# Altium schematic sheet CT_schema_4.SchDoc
size 298 x 230 mm
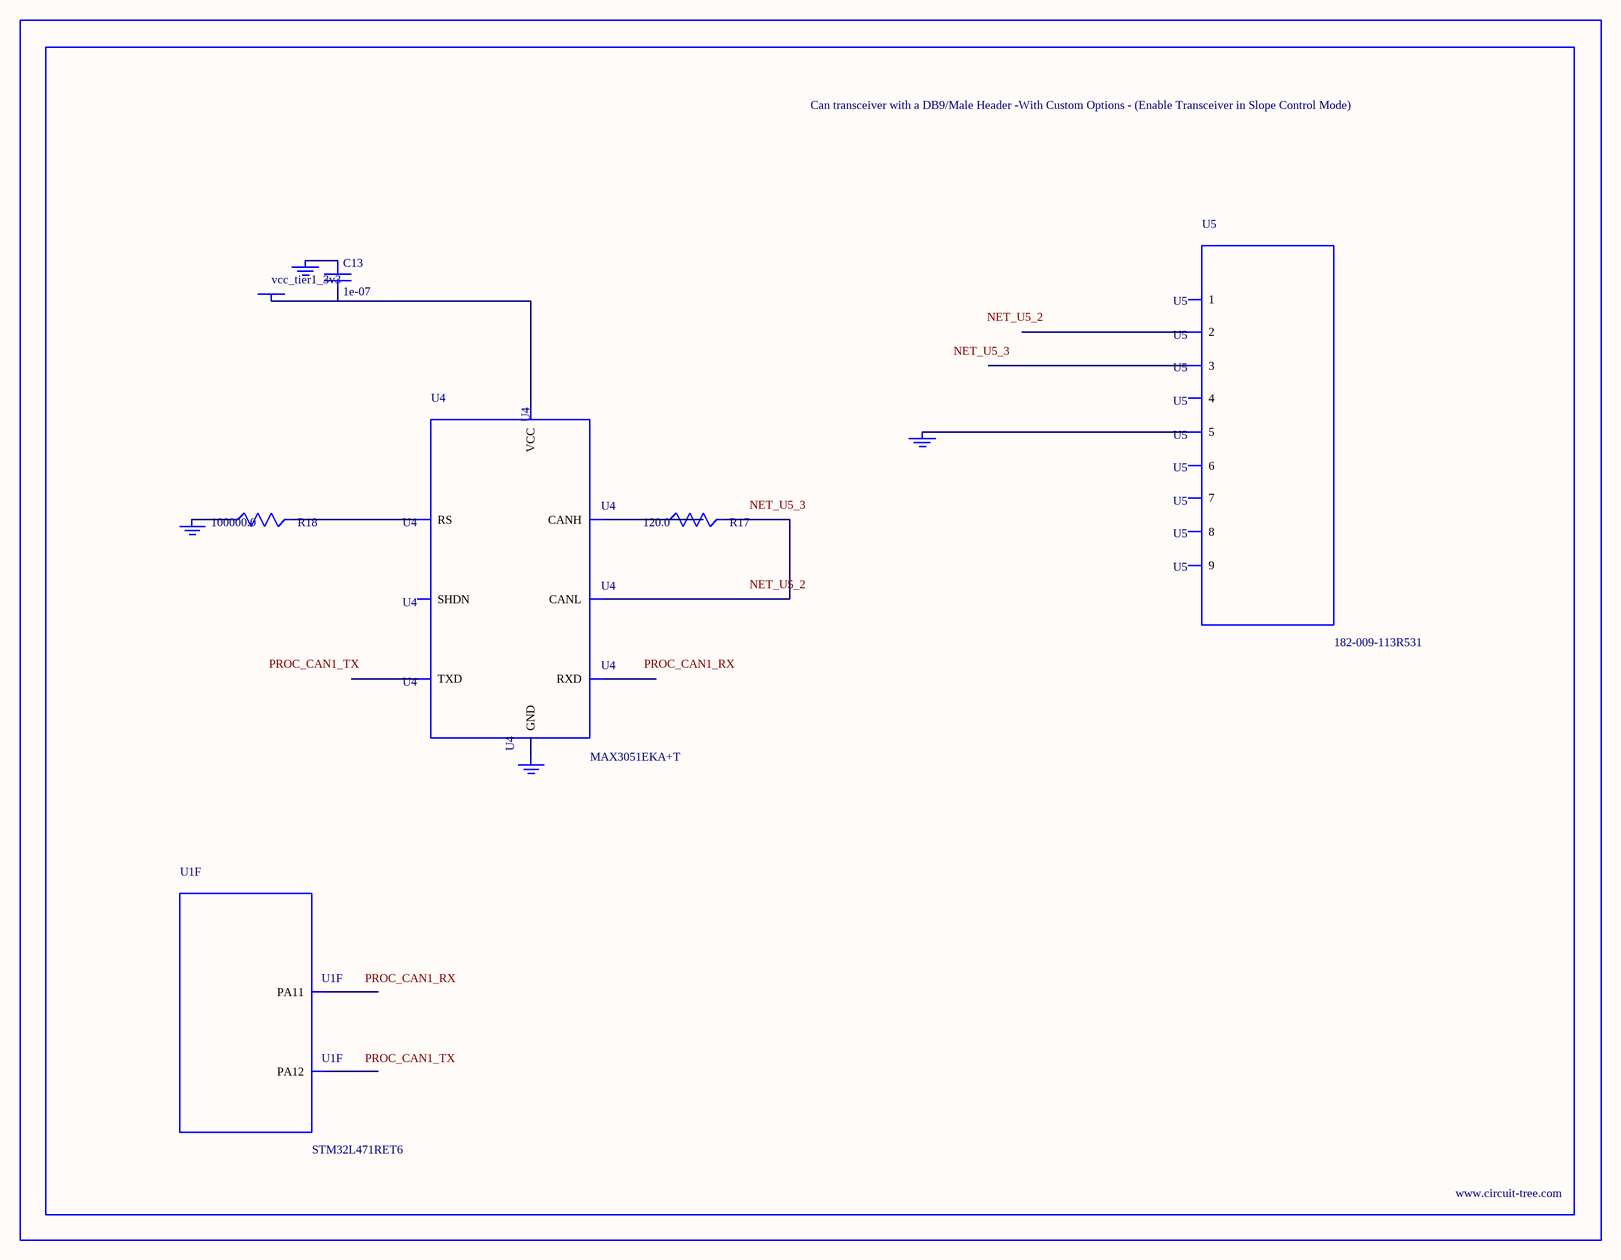
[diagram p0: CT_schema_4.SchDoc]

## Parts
BORDER3  (no value)
C13  1e-07  [C0402]
GND_INSTANCE_3_0  (no value)
GND_INSTANCE_3_1  (no value)
GND_INSTANCE_3_2  (no value)
GND_INSTANCE_3_3  (no value)
POWER_INSTANCE_3_0  vcc_tier1_3v3
R17  120.0  [R0603]
R18  100000.0  [R0603]
U1  STM32L471RET6  [LQFP64]  (part F of 8)
U4  MAX3051EKA+T  [SOT-23-8]
U5  182-009-113R531  [182-009-MALE]

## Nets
NetC13_1: C13.1 GND_INSTANCE_3_0.0(GND)
NetC13_2: C13.2 POWER_INSTANCE_3_0.0(PWR) U4.3(VCC)
NetGND_INSTANCE_3_1_0: GND_INSTANCE_3_1.0(GND) R18.1
NetGND_INSTANCE_3_2_0: GND_INSTANCE_3_2.0(GND) U4.2(GND)
NetGND_INSTANCE_3_3_0: GND_INSTANCE_3_3.0(GND) U5.5
NetR17_1: R17.1 U4.7(CANH)
NetR17_2: R17.2 U4.6(CANL)
NetR18_2: R18.2 U4.8(RS)

Not connected (* = marked no-connect by the designer): U1 44(PA11) 45(PA12); U4 1(TXD) 4(RXD) 5(SHDN); U5 1 2 3 4 6 7 8 9

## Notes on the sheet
- Labels drawn without touching a wire or pin: NET_U5_2, NET_U5_3, PROC_CAN1_RX, PROC_CAN1_TX

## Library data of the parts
BORDER3 = BORDER_PAGE3
C13 = C0402C104K3RACTU
GND_INSTANCE_3_0-GND_INSTANCE_3_3 = GND
POWER_INSTANCE_3_0 = PWR
R17 = RC0603JR-07120RL
R18 = RC0603JR-07100KL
